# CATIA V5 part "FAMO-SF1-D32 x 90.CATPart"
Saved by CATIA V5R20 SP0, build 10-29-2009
Part number: FAMO-SF1-D32 x 90
Definition: NONE
Nomenclature: FAMO-SF1-D32 x 90
Source: Unknown
Description: FAMO-SF1-D32 x 90
Bounding box of the stored display mesh (mm): x -53 to 37, y -26.5 to 26.5, z -26.5 to 26.5
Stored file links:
  C:\Users\Utente\Desktop\IO LAVORO\3D X SITO CF\X SITO\FAMO\FAMO-SF1-D32 x 90.CATPart
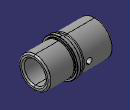
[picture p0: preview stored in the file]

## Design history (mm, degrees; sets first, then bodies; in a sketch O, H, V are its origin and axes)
Body1 "FAMO-SF1-D32 x 90" (main body)
  Solid1: solid without history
